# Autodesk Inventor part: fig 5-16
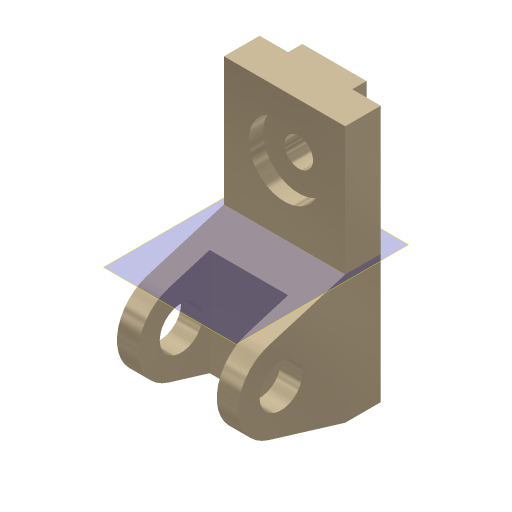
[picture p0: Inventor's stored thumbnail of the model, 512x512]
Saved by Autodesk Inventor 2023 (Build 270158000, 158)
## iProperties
Created: 2001-11
Part Number: fig 5-16
Document SubType Name: Modeling
Designer: Renu Muthoo
Density: 1 g/cm^3
Material: Generic
Appearance: Metal-Titanium (Polished)
Control State: 0
Master: False
Checked Out: False
Shininess: 65.0
Angle Display Precision: 2
Document Length Units: 11269
Document Angle Units: 11279
Document Time Units: 11290
Document Mass Units: 11283
Document Length Units Precision: 3
Document Angle Units Precision: 2
Compacted: False
Density: 0.0
Volumn: 0.0
Area: 0.0
PropertySet Name: Model Information
Author: Renu Muthoo
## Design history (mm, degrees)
node "Sketch1"
sketch "Sketch2"
  geometry: L1 (33.257, 104.664)-(33.257, -75.336); L2 (33.257, -75.336)-(8.257, -75.336); L3 (8.257, -75.336)-(-45.451, -59.045); L4 (-45.451, -1.628)-(8.257, 14.664); L5 (8.257, 14.664)-(8.257, 104.664); L6 (8.257, 104.664)-(33.257, 104.664); C1 r 15 at (-36.743, -30.336); A1 r 30 centre (-36.743, -30.336) between (-45.451, -1.628) and (-45.451, -59.045)
  constraints: 12 end point, 2 centre point, 2 equal length, 2 parallel, 2 point on circle, 2 tangent, 1 coincident, 1 perpendicular, 1 vertical
  dimensions: "d0" = 180 distance of L1.start L1.end; "d1" = 30 radius of A1; "d2" = 25 distance of L5.end L1.start; "d3" = 45 distance from line of L2 A1.centre; "d4" = 70 distance from line of L1 A1.centre; "d5" = 30 diameter of C1
extrude "Extrusion1" new body sketch "Sketch2" distance "d6" = 85; taper "d7" = 0 deg
workplane "Work Plane1"
sketch "Sketch3"
  geometry: L1 (15, 62.364)-(70, 62.364); L2 (70, 62.364)-(70, -52.386); L3 (70, -52.386)-(15, -52.386); L4 (15, -52.386)-(15, 62.364); L5 (0, -45)-(0, -28.708) reference
  constraints: 8 end point, 2 parallel, 1 horizontal, 1 perpendicular
  dimensions: "d8" = 55 distance of L1.start L1.end; "d9" = 15 distance between parallel lines of L5 L4
extrude "Extrusion2" cut sketch "Sketch3" distance "d10" = 50; taper "d11" = 0 deg
sketch "Sketch4"
  geometry: L1 (0, 25)-(85, 25) reference; L2 (0, 0)-(0, 25) reference; L3 (20, 25)-(65, 25); L4 (65, 25)-(65, 35); L5 (65, 35)-(20, 35); L6 (20, 35)-(20, 25)
  constraints: 8 end point, 2 parallel, 1 horizontal, 1 perpendicular, 1 point on line
  dimensions: "d12" = 45 distance of L4.end L5.end; "d13" = 10 distance of L3.end L4.end; "d14" = 20 distance between parallel lines of L2 L6
extrude "Extrusion3" join sketch "Sketch4" stored distance "d15" = 50; taper "d16" = 0 deg
sketch "Sketch5"
  geometry: L1 (85, 0)-(85, 90) reference; L2 (0, 90)-(85, 90) reference; 1 further point
  dimensions: "d17" = 42 distance from line of L2 point (42.5, 48); "d18" = 42.5 distance from line of L1 point (42.5, 48)
hole "Hole1" sketch "Sketch5" at (42.5, 48) diameter "d19" = 20; stored, may be unused: countersink angle "d23" = 82 deg, drill point angle "d25" = 118 deg; dims "d20" = 6, "d21" = 50, "d22" = 10, "d24" = 8
workplane "Work Plane7"
body "Solid1"
other parameters: "d27" = 90 deg
